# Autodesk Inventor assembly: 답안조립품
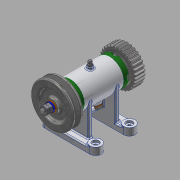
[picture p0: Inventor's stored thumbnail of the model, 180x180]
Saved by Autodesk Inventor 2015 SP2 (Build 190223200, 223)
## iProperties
Created: 2015-11
Part Number: 답안조립품
Document SubType Name: Assembly
Designer: AMC
Author: AMC
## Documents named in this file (16)
- C:\Users\AMC\Desktop\451109V1032\답안조립품.iam
- C:\Users\AMC\Desktop\451109V1032\본체.ipt
- C:\Users\AMC\Desktop\451109V1032\스퍼기어.ipt
- C:\Users\AMC\Desktop\451109V1032\커버.ipt
- C:\Users\AMC\Desktop\451109V1032\베어링 15 x 32 x 9.ipt
- C:\Users\AMC\Desktop\451109V1032\축.ipt
- C:\Users\AMC\Desktop\451109V1032\니플 M 6 x 0.75.ipt
- C:\Users\AMC\Desktop\451109V1032\볼트 M4 x 12.ipt
- C:\Users\AMC\Desktop\451109V1032\와셔 6x11.5.ipt
- C:\Users\AMC\Desktop\451109V1032\볼트 M 6 x 8.ipt
- C:\Users\AMC\Desktop\451109V1032\키 3 x 3 x 12.ipt
- C:\Users\AMC\Desktop\451109V1032\와셔 8x17.ipt
- C:\Users\AMC\Desktop\451109V1032\스프링와셔 8.ipt
- C:\Users\AMC\Desktop\451109V1032\너트 M 8.ipt
- C:\Users\AMC\Desktop\451109V1032\V벨트풀리.ipt
- C:\Users\AMC\Desktop\451109V1032\오일 실 15 25 7.ipt
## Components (11 placed, 3 different names)
1. KS B 2023 6002 - 15 x 32 x 9:1
2. KS B 2023 6002 - 15 x 32 x 9:2
3. V벨트풀리:1
4. ISO 4762 M4 x 12:1
5. ISO 4762 M4 x 12:2
6. ISO 4762 M4 x 12:3
7. ISO 4762 M4 x 12:4
8. ISO 4762 M4 x 12:5
9. ISO 4762 M4 x 12:6
10. ISO 4762 M4 x 12:7
11. ISO 4762 M4 x 12:8
